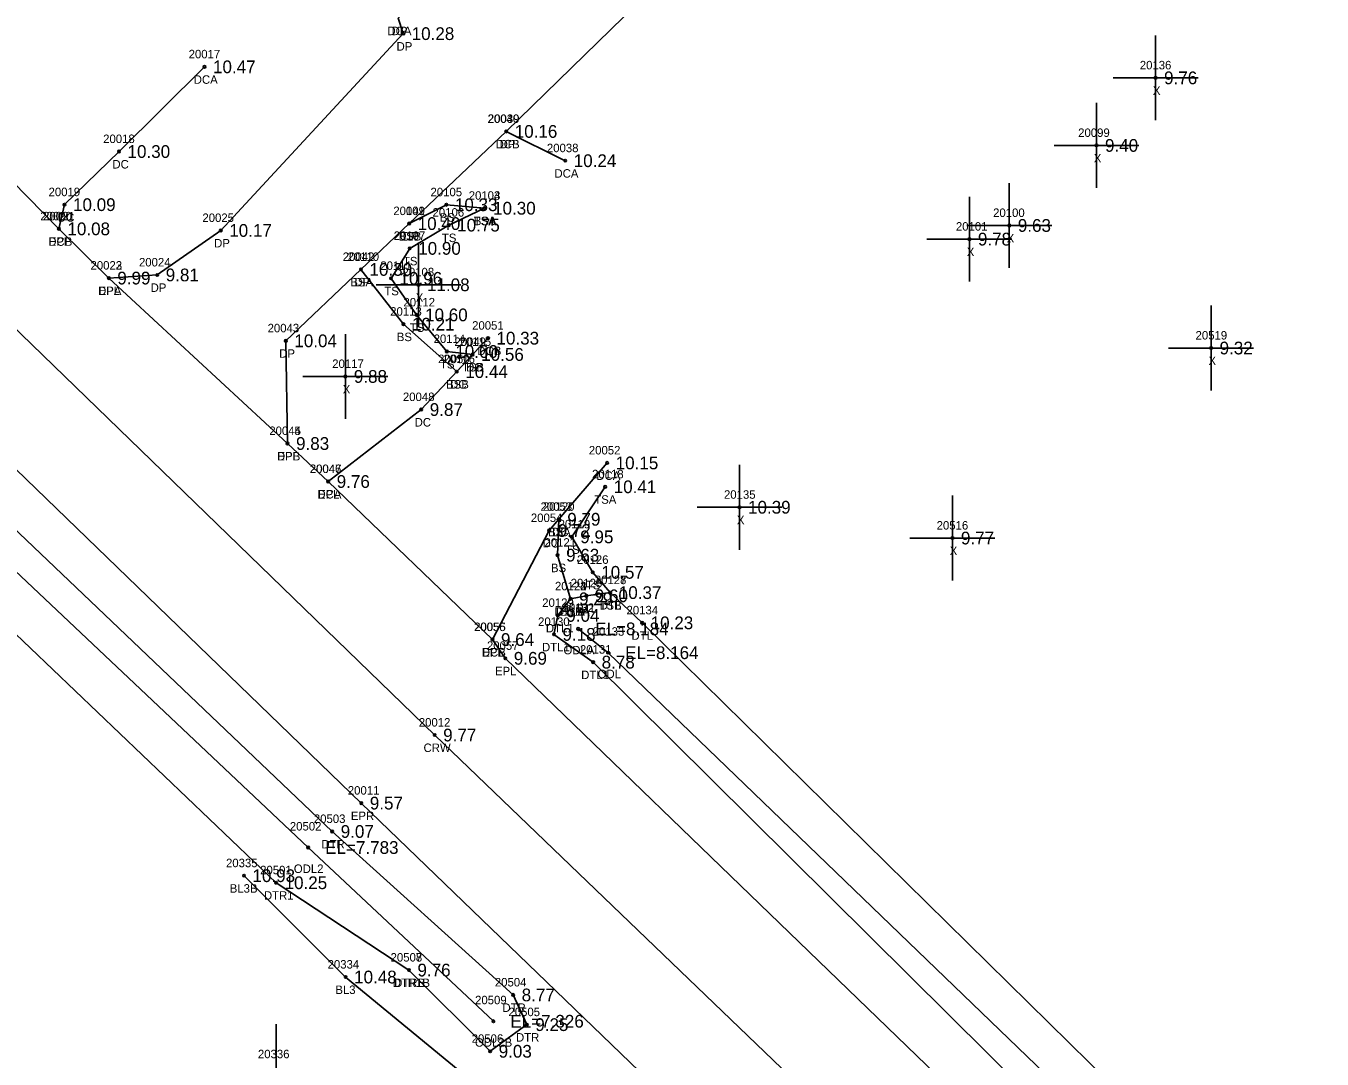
# Model space of a CAD drawing. Extents: x 2608745 to 2610333, y 641917 to 643463.
# Drawn here: x 2608842.3 to 2608995, y 643262.1 to 643383.8 of the extents above; entities that cross this region are included whole.
import ezdxf

# ---------------------------------------------------------------- set-up
doc = ezdxf.new("R2010")
doc.units = 0
for name, color, linetype in [('RD_DTM_BkLn1', 7, 'Continuous'), ('RD_DTM_BkLn2', 7, 'Continuous'), ('RD_DTM_BkLn_txCode', 7, 'Continuous'), ('RD_EX_Conc', 7, 'Continuous'), ('RD_EX_Conc_txCode', 7, 'Continuous'), ('RD_EX_Driveway', 7, 'Continuous'), ('RD_EX_Driveway_txCode', 7, 'Continuous'), ('RD_EX_H2O', 7, 'Continuous'), ('RD_EX_H2O_txCode', 7, 'Continuous'), ('RD_EX_Misc', 7, 'Continuous'), ('RD_EX_Misc_txCode', 7, 'Continuous'), ('RD_EX_Road', 7, 'Continuous'), ('RD_EX_Road_txCode', 7, 'Continuous'), ('RD_EX_TX_Conc_ELEV', 7, 'Continuous'), ('RD_EX_TX_Driveway_ELEV', 7, 'Continuous'), ('RD_EX_TX_H2O_ELEV', 7, 'Continuous'), ('RD_EX_TX_Misc_ELEV', 7, 'Continuous'), ('RD_EX_TX_Road_ELEV', 7, 'Continuous'), ('RD_HC_Survey_ELEV', 7, 'Continuous'), ('RD_HC_Survey_txCode', 7, 'Continuous'), ('RD_SMD_Locator', 7, 'Continuous')]:
    doc.layers.add(name, color=color, linetype=linetype)

msp = doc.modelspace()

# ---------------------------------------------------------------- linework, layer by layer
at = {"layer": 'RD_DTM_BkLn1'}
for points in [[(2608814.73, 643373.65), (2608890.45, 643300.26), (2608962.19, 643231.31), (2609034.91, 643161.19), (2609108.48, 643089.9), (2609179.19, 643022.29), (2609255.71, 642948.78), (2609335.19, 642871.73), (2609410.7, 642798.48), (2609491.67, 642719.95), (2609518.07, 642695.15)], [(2608899.44, 643255.71), (2608879.96, 643271.75), (2608867.99, 643283.69)]]:
    msp.add_lwpolyline(points, dxfattribs=at)
at = {"layer": 'RD_DTM_BkLn2'}
for points in [[(2608896.33, 643362.33), (2608891.83, 643362.74), (2608887.45, 643360.52)], [(2608896.33, 643362.33), (2608892.1, 643360.34), (2608887.51, 643357.6), (2608885.31, 643354.07), (2608888.32, 643349.76), (2608891.88, 643345.45), (2608894.93, 643345.1)], [(2608881.77, 643355.12), (2608886.77, 643348.67), (2608893.05, 643343.08)], [(2608910.54, 643329.51), (2608906.6, 643323.61), (2608909.07, 643319.43), (2608911.14, 643317.04)], [(2608905.07, 643325.68), (2608904.93, 643321.45), (2608906.46, 643316.31)]]:
    msp.add_lwpolyline(points, dxfattribs=at)
at = {"layer": 'RD_EX_Conc'}
msp.add_line((2608905.83, 643367.93), (2608898.88, 643371.38), dxfattribs=at)
for points in [[(2608863.34, 643378.99), (2608853.27, 643369.01), (2608846.85, 643362.75), (2608846.19, 643359.9)], [(2608877.91, 643330.13), (2608888.87, 643338.61), (2608894.93, 643345.1), (2608893.05, 643343.08), (2608896.73, 643347.02)], [(2608910.77, 643332.32), (2608905.07, 643325.68), (2608903.94, 643324.36), (2608897.26, 643311.51)]]:
    msp.add_lwpolyline(points, dxfattribs=at)
at = {"layer": 'RD_EX_Driveway'}
for points in [[(2608852.07, 643354.1), (2608857.77, 643354.47), (2608865.25, 643359.71), (2608886.74, 643382.9), (2608886.16, 643384.72), (2608908.71, 643407.59), (2608922.16, 643418.7)], [(2608933.79, 643406.58), (2608920.41, 643392.44), (2608898.88, 643371.38), (2608887.45, 643360.52), (2608881.77, 643355.12), (2608872.92, 643346.71), (2608873.12, 643334.61)]]:
    msp.add_lwpolyline(points, dxfattribs=at)
at = {"layer": 'RD_EX_H2O'}
for points in [[(2608820.55, 643343.99), (2608817.4, 643346.33), (2608813.82, 643346.05), (2608811.24, 643342.85), (2608813.01, 643339.53), (2608816.5, 643335.64), (2608871.77, 643282.86), (2608887.42, 643272.57)], [(2608820.55, 643343.99), (2608878.38, 643288.9), (2608899.7, 643269.64), (2608901.3, 643266.14), (2608896.99, 643263), (2608887.42, 643272.57)], [(2608817.01, 643342.27), (2608875.55, 643287.01), (2608897.37, 643266.54)], [(2608906.46, 643316.31), (2608908.31, 643316.67), (2608911.14, 643317.04), (2608914.89, 643313.48), (2608979.58, 643249.87), (2609010.65, 643218.64)], [(2608906.46, 643316.31), (2608904.96, 643314.36), (2608904.5, 643312.12), (2608909.12, 643308.85), (2608974.26, 643244.24), (2609005.73, 643214.72), (2609009.05, 643211.6), (2609010.84, 643213.4), (2609012.56, 643215.9), (2609010.65, 643218.64)], [(2608907.36, 643312.77), (2608910.89, 643309.96), (2608976.29, 643246.9), (2609008.79, 643215.13)]]:
    msp.add_lwpolyline(points, dxfattribs=at)
at = {"layer": 'RD_EX_Misc'}
for p, q in [((2608975.37, 643372.69), (2608975.37, 643382.69)), ((2608970.37, 643377.69), (2608980.37, 643377.69)), ((2608968.41, 643364.73), (2608968.41, 643374.73)), ((2608963.41, 643369.73), (2608973.41, 643369.73)), ((2608958.14, 643355.3), (2608958.14, 643365.3)), ((2608953.44, 643353.69), (2608953.44, 643363.69)), ((2608953.14, 643360.3), (2608963.14, 643360.3)), ((2608888.55, 643348.31), (2608888.55, 643358.31)), ((2608948.44, 643358.69), (2608958.44, 643358.69)), ((2608883.55, 643353.31), (2608893.55, 643353.31)), ((2608981.91, 643340.86), (2608981.91, 643350.86)), ((2608879.93, 643337.51), (2608879.93, 643347.51)), ((2608976.91, 643345.86), (2608986.91, 643345.86)), ((2608874.93, 643342.51), (2608884.93, 643342.51)), ((2608926.36, 643322.1), (2608926.36, 643332.1)), ((2608951.44, 643318.47), (2608951.44, 643328.47)), ((2608921.36, 643327.1), (2608931.36, 643327.1)), ((2608946.44, 643323.47), (2608956.44, 643323.47)), ((2608871.77, 643256.18), (2608871.77, 643266.18))]:
    msp.add_line(p, q, dxfattribs=at)
at = {"layer": 'RD_EX_Road'}
for points in [[(2608823.57, 643381.9), (2608829.58, 643376.81), (2608846.19, 643359.9), (2608852.07, 643354.1), (2608873.12, 643334.61), (2608877.91, 643330.13), (2608897.26, 643311.51), (2608898.77, 643309.3), (2608970.3, 643240.18), (2609042.49, 643170.94), (2609058.51, 643155.46), (2609096.06, 643119.37)], [(2608806.89, 643364.99), (2608810.18, 643361.1), (2608820.75, 643351.25), (2608881.81, 643292.24), (2608917.83, 643257.49), (2608933.21, 643242.71), (2608954.07, 643222.83), (2609026.06, 643154.19), (2609039.6, 643139.96), (2609073.88, 643106.95), (2609100.48, 643081.89), (2609124.19, 643058.87), (2609171.61, 643013.71), (2609183.19, 643002.28), (2609197.91, 642988.37), (2609247.59, 642940.95), (2609328.02, 642863.6), (2609402.61, 642790.3), (2609474.23, 642720.69), (2609483.84, 642711.58), (2609495.78, 642699.92), (2609509.81, 642686.45)]]:
    msp.add_lwpolyline(points, dxfattribs=at)
at = {"layer": 'RD_SMD_Locator'}
for centre in [(2608886.74, 643382.9), (2608863.34, 643378.99), (2608975.37, 643377.69), (2608898.88, 643371.38), (2608898.88, 643371.38), (2608853.27, 643369.01), (2608968.41, 643369.73), (2608905.83, 643367.93), (2608846.85, 643362.75), (2608891.83, 643362.74), (2608896.33, 643362.33), (2608896.33, 643362.33), (2608846.19, 643359.9), (2608846.19, 643359.9), (2608865.25, 643359.71), (2608887.45, 643360.52), (2608887.45, 643360.52), (2608892.1, 643360.34), (2608958.14, 643360.3), (2608953.44, 643358.69), (2608887.51, 643357.6), (2608881.77, 643355.12), (2608881.77, 643355.12), (2608852.07, 643354.1), (2608852.07, 643354.1), (2608857.77, 643354.47), (2608885.31, 643354.07), (2608888.55, 643353.31), (2608886.77, 643348.67), (2608888.32, 643349.76), (2608872.92, 643346.71), (2608896.73, 643347.02), (2608981.91, 643345.86), (2608891.88, 643345.45), (2608894.93, 643345.1), (2608894.93, 643345.1), (2608879.93, 643342.51), (2608893.05, 643343.08), (2608893.05, 643343.08), (2608888.87, 643338.61), (2608873.12, 643334.61), (2608873.12, 643334.61), (2608910.77, 643332.32), (2608877.91, 643330.13), (2608877.91, 643330.13), (2608910.54, 643329.51), (2608926.36, 643327.1), (2608903.94, 643324.36), (2608905.07, 643325.68), (2608905.07, 643325.68), (2608906.6, 643323.61), (2608951.44, 643323.47), (2608904.93, 643321.45), (2608909.07, 643319.43), (2608908.31, 643316.67), (2608911.14, 643317.04), (2608911.14, 643317.04), (2608906.46, 643316.31), (2608906.46, 643316.31), (2608906.46, 643316.31), (2608904.96, 643314.36), (2608904.5, 643312.12), (2608907.36, 643312.77), (2608914.89, 643313.48), (2608897.26, 643311.51), (2608897.26, 643311.51), (2608898.77, 643309.3), (2608910.89, 643309.96), (2608909.12, 643308.85), (2608890.45, 643300.26), (2608881.81, 643292.24), (2608878.38, 643288.9), (2608875.55, 643287.01), (2608867.99, 643283.69), (2608871.77, 643282.86), (2608887.42, 643272.57), (2608887.42, 643272.57), (2608879.96, 643271.75), (2608899.7, 643269.64), (2608897.37, 643266.54), (2608901.3, 643266.14), (2608896.99, 643263)]:
    msp.add_circle(centre, 0.15, dxfattribs=at)

# ---------------------------------------------------------------- texts
at = {"layer": 'RD_DTM_BkLn_txCode'}
for s, p in [('20105', (2608889.96, 643363.74)), ('20103', (2608894.46, 643363.33)), ('20104', (2608894.46, 643363.33)), ('20109', (2608885.58, 643361.52)), ('20106', (2608890.2, 643361.34)), ('BS', (2608891.05, 643360.74)), ('TSA', (2608895.05, 643360.33)), ('BSA', (2608895.06, 643360.33)), ('20107', (2608885.63, 643358.6)), ('BSB', (2608886.2, 643358.52)), ('TS', (2608891.3, 643358.34)), ('20110', (2608880.18, 643356.12)), ('TS', (2608886.71, 643355.6)), ('20111', (2608884.05, 643355.07)), ('BSA', (2608880.51, 643353.12)), ('TS', (2608884.52, 643352.07)), ('20113', (2608885.21, 643349.67)), ('20112', (2608886.77, 643350.76)), ('TS', (2608887.52, 643347.76)), ('BS', (2608885.99, 643346.67)), ('20114', (2608890.33, 643346.45)), ('20115', (2608893.38, 643346.1)), ('TS', (2608891.08, 643343.45)), ('20116', (2608891.48, 643344.08)), ('TSB', (2608893.66, 643343.1)), ('BSB', (2608891.8, 643341.08)), ('20118', (2608908.99, 643330.51)), ('20120', (2608903.2, 643326.68)), ('TSA', (2608909.25, 643327.51)), ('BSA', (2608903.81, 643323.68)), ('20119', (2608905.05, 643324.61)), ('20121', (2608903.38, 643322.45)), ('TS', (2608905.81, 643321.61)), ('20126', (2608907.21, 643320.43)), ('BS', (2608904.15, 643319.45)), ('20122', (2608904.62, 643317.31)), ('TS', (2608908.27, 643317.43)), ('20127', (2608909.31, 643318.04)), ('BSB', (2608905.21, 643314.31)), ('TSB', (2608909.87, 643315.04)), ('20335', (2608865.87, 643284.69)), ('BL3B', (2608866.31, 643281.69)), ('20334', (2608877.84, 643272.75)), ('BL3', (2608878.75, 643269.75))]:
    msp.add_text(s, height=1, dxfattribs=at).set_placement(p)
at = {"layer": 'RD_EX_Conc_txCode'}
for s, p in [('DCA', (2608884.89, 643382.72)), ('20017', (2608861.47, 643379.99)), ('DCA', (2608862.07, 643376.99)), ('20039', (2608896.72, 643372.38)), ('20018', (2608851.4, 643370.01)), ('DCB', (2608897.63, 643369.38)), ('20038', (2608903.67, 643368.93)), ('DC', (2608852.49, 643367.01)), ('DCA', (2608904.56, 643365.93)), ('20019', (2608844.97, 643363.75)), ('20020', (2608844, 643360.9)), ('DC', (2608846.07, 643360.75)), ('DCB', (2608844.94, 643357.9)), ('20051', (2608894.86, 643348.02)), ('20049', (2608892.77, 643346.1)), ('DCB', (2608895.48, 643345.02)), ('20050', (2608890.85, 643344.08)), ('DC', (2608894.15, 643343.1)), ('DC', (2608892.27, 643341.08)), ('20048', (2608886.71, 643339.61)), ('DC', (2608888.09, 643336.61)), ('20052', (2608908.61, 643333.32)), ('20047', (2608875.75, 643331.13)), ('DCA', (2608909.5, 643330.32)), ('DCA', (2608876.64, 643328.13)), ('20053', (2608902.92, 643326.68)), ('20054', (2608901.78, 643325.36)), ('DC', (2608904.29, 643323.68)), ('DC', (2608903.16, 643322.36)), ('20055', (2608895.11, 643312.51)), ('DCB', (2608896.01, 643309.51))]:
    msp.add_text(s, height=1, dxfattribs=at).set_placement(p)
at = {"layer": 'RD_EX_Driveway_txCode'}
for s, p in [('DP', (2608885.38, 643382.72)), ('DP', (2608885.96, 643380.9)), ('20040', (2608896.68, 643372.38)), ('DP', (2608898.1, 643369.38)), ('20041', (2608885.58, 643361.52)), ('20025', (2608863.09, 643360.71)), ('DP', (2608886.67, 643358.52)), ('DP', (2608864.47, 643357.71)), ('20024', (2608855.62, 643355.47)), ('20042', (2608879.62, 643356.12)), ('20023', (2608849.91, 643355.1)), ('DP', (2608856.99, 643352.47)), ('DP', (2608880.99, 643353.12)), ('DPA', (2608850.8, 643352.1)), ('20043', (2608870.77, 643347.71)), ('DP', (2608872.14, 643344.71)), ('20044', (2608870.97, 643335.61)), ('DPB', (2608871.87, 643332.61))]:
    msp.add_text(s, height=1, dxfattribs=at).set_placement(p)
at = {"layer": 'RD_EX_H2O_txCode'}
for s, p in [('20123', (2608904.62, 643317.31)), ('20124', (2608904.62, 643317.31)), ('20125', (2608906.47, 643317.67)), ('20128', (2608909.31, 643318.04)), ('20129', (2608903.12, 643315.36)), ('DTL1A', (2608904.56, 643314.31)), ('DTLA', (2608904.73, 643314.31)), ('20132', (2608905.52, 643314.77)), ('DTL', (2608907.06, 643314.67)), ('DTL', (2608909.9, 643315.04)), ('20134', (2608913.05, 643314.48)), ('20130', (2608902.63, 643313.12)), ('DTL1', (2608903.55, 643312.36)), ('20133', (2608909.06, 643311.96)), ('DTL', (2608913.64, 643311.48)), ('DTL1', (2608903.09, 643310.12)), ('ODLA', (2608905.62, 643309.77)), ('20131', (2608907.56, 643309.85)), ('DTL1', (2608907.71, 643306.85)), ('ODL', (2608909.65, 643306.96)), ('20503', (2608876.22, 643289.9)), ('20502', (2608873.39, 643289.01)), ('DTR', (2608877.11, 643286.9)), ('20501', (2608869.89, 643283.86)), ('ODL2', (2608873.86, 643284.01)), ('DTR1', (2608870.34, 643280.86)), ('20507', (2608885.26, 643273.57)), ('20508', (2608885.26, 643273.57)), ('DTR1B', (2608885.51, 643270.57)), ('DTRB', (2608885.68, 643270.57)), ('20504', (2608897.54, 643270.64)), ('20509', (2608895.21, 643268.54)), ('DTR', (2608898.43, 643267.64)), ('20505', (2608899.14, 643267.14)), ('20506', (2608894.81, 643264)), ('DTR', (2608900.03, 643264.14)), ('ODL2B', (2608895.2, 643263.54))]:
    msp.add_text(s, height=1, dxfattribs=at).set_placement(p)
at = {"layer": 'RD_EX_Misc_txCode'}
for s, p in [('20136', (2608973.51, 643378.69)), ('X', (2608975.05, 643375.69)), ('20099', (2608966.25, 643370.73)), ('X', (2608968.09, 643367.73)), ('20100', (2608956.23, 643361.3)), ('20101', (2608951.85, 643359.69)), ('X', (2608957.83, 643358.3)), ('X', (2608953.13, 643356.69)), ('20108', (2608886.67, 643354.31)), ('X', (2608888.23, 643351.31)), ('20519', (2608980.08, 643346.86)), ('20117', (2608878.38, 643343.51)), ('X', (2608981.6, 643343.86)), ('X', (2608879.62, 643340.51)), ('20135', (2608924.53, 643328.1)), ('X', (2608926.05, 643325.1)), ('20516', (2608949.58, 643324.47)), ('X', (2608951.12, 643321.47)), ('20336', (2608869.63, 643262.18))]:
    msp.add_text(s, height=1, dxfattribs=at).set_placement(p)
at = {"layer": 'RD_EX_Road_txCode'}
for s, p in [('20021', (2608844.32, 643360.9)), ('EPL', (2608844.99, 643357.9)), ('20022', (2608849.91, 643355.1)), ('EPL', (2608850.86, 643352.1)), ('20045', (2608870.97, 643335.61)), ('EPL', (2608871.92, 643332.61)), ('20046', (2608875.73, 643331.13)), ('EPL', (2608876.71, 643328.13)), ('20056', (2608895.08, 643312.51)), ('20057', (2608896.61, 643310.3)), ('EPL', (2608896.06, 643309.51)), ('EPL', (2608897.56, 643307.3)), ('20011', (2608880.22, 643293.24)), ('EPR', (2608880.58, 643290.24))]:
    msp.add_text(s, height=1, dxfattribs=at).set_placement(p)
at = {"layer": 'RD_EX_TX_Conc_ELEV'}
for s, p in [('10.47', (2608864.34, 643378.24)), ('10.16', (2608899.88, 643370.63)), ('10.30', (2608854.27, 643368.26)), ('10.24', (2608906.83, 643367.18)), ('10.09', (2608847.85, 643362)), ('10.08', (2608847.19, 643359.15)), ('10.33', (2608897.73, 643346.27)), ('10.56', (2608895.93, 643344.35)), ('10.44', (2608894.05, 643342.33)), ('9.87', (2608889.87, 643337.86)), ('10.15', (2608911.77, 643331.57)), ('9.76', (2608878.91, 643329.38)), ('9.79', (2608906.07, 643324.93)), ('9.72', (2608904.94, 643323.61)), ('9.64', (2608898.26, 643310.76))]:
    msp.add_text(s, height=1.5, dxfattribs=at).set_placement(p)
at = {"layer": 'RD_EX_TX_Driveway_ELEV'}
for s, p in [('10.28', (2608887.74, 643382.15)), ('10.16', (2608899.88, 643370.63)), ('10.40', (2608888.45, 643359.77)), ('10.17', (2608866.25, 643358.96)), ('9.99', (2608853.07, 643353.35)), ('9.81', (2608858.77, 643353.72)), ('10.30', (2608882.77, 643354.37)), ('10.04', (2608873.92, 643345.96)), ('9.83', (2608874.12, 643333.86))]:
    msp.add_text(s, height=1.5, dxfattribs=at).set_placement(p)
at = {"layer": 'RD_EX_TX_H2O_ELEV'}
for s, p in [('9.29', (2608907.46, 643315.56)), ('9.29', (2608907.46, 643315.56)), ('9.60', (2608909.31, 643315.92)), ('10.37', (2608912.14, 643316.29)), ('9.04', (2608905.96, 643313.61)), ('10.23', (2608915.89, 643312.73)), ('9.18', (2608905.5, 643311.37)), ('EL=8.184', (2608909.36, 643312.02)), ('EL=8.164', (2608912.89, 643309.21)), ('8.78', (2608910.12, 643308.1)), ('9.07', (2608879.38, 643288.15)), ('EL=7.783', (2608877.55, 643286.26)), ('10.25', (2608872.77, 643282.11)), ('9.76', (2608888.42, 643271.82)), ('9.76', (2608888.42, 643271.82)), ('8.77', (2608900.7, 643268.89)), ('EL=7.326', (2608899.37, 643265.79)), ('9.25', (2608902.3, 643265.39)), ('9.03', (2608897.99, 643262.25))]:
    msp.add_text(s, height=1.5, dxfattribs=at).set_placement(p)
at = {"layer": 'RD_EX_TX_Misc_ELEV'}
for s, p in [('9.76', (2608976.37, 643376.94)), ('9.40', (2608969.41, 643368.98)), ('10.33', (2608892.83, 643361.99)), ('10.30', (2608897.33, 643361.58)), ('10.30', (2608897.33, 643361.58)), ('10.40', (2608888.45, 643359.77)), ('10.75', (2608893.1, 643359.59)), ('9.63', (2608959.14, 643359.55)), ('9.78', (2608954.44, 643357.94)), ('10.90', (2608888.51, 643356.85)), ('10.30', (2608882.77, 643354.37)), ('10.96', (2608886.31, 643353.32)), ('11.08', (2608889.55, 643352.56)), ('10.60', (2608889.32, 643349.01)), ('10.21', (2608887.77, 643347.92)), ('10.60', (2608892.88, 643344.7)), ('10.56', (2608895.93, 643344.35)), ('9.32', (2608982.91, 643345.11)), ('9.88', (2608880.93, 643341.76)), ('10.44', (2608894.05, 643342.33)), ('10.41', (2608911.54, 643328.76)), ('10.39', (2608927.36, 643326.35)), ('9.79', (2608906.07, 643324.93)), ('9.95', (2608907.6, 643322.86)), ('9.77', (2608952.44, 643322.72)), ('9.63', (2608905.93, 643320.7)), ('10.57', (2608910.07, 643318.68)), ('9.29', (2608907.46, 643315.56)), ('10.37', (2608912.14, 643316.29)), ('10.93', (2608868.99, 643282.94)), ('10.48', (2608880.96, 643271))]:
    msp.add_text(s, height=1.5, dxfattribs=at).set_placement(p)
at = {"layer": 'RD_EX_TX_Road_ELEV'}
for s, p in [('10.08', (2608847.19, 643359.15)), ('9.99', (2608853.07, 643353.35)), ('9.83', (2608874.12, 643333.86)), ('9.76', (2608878.91, 643329.38)), ('9.64', (2608898.26, 643310.76)), ('9.69', (2608899.77, 643308.55)), ('9.57', (2608882.81, 643291.49))]:
    msp.add_text(s, height=1.5, dxfattribs=at).set_placement(p)
at = {"layer": 'RD_HC_Survey_ELEV'}
msp.add_text('9.77', height=1.5, dxfattribs=at).set_placement((2608891.45, 643299.51))
at = {"layer": 'RD_HC_Survey_txCode'}
for s, p in [('20012', (2608888.58, 643301.26)), ('CRW', (2608889.14, 643298.26))]:
    msp.add_text(s, height=1, dxfattribs=at).set_placement(p)

doc.saveas('drawing.dxf')
